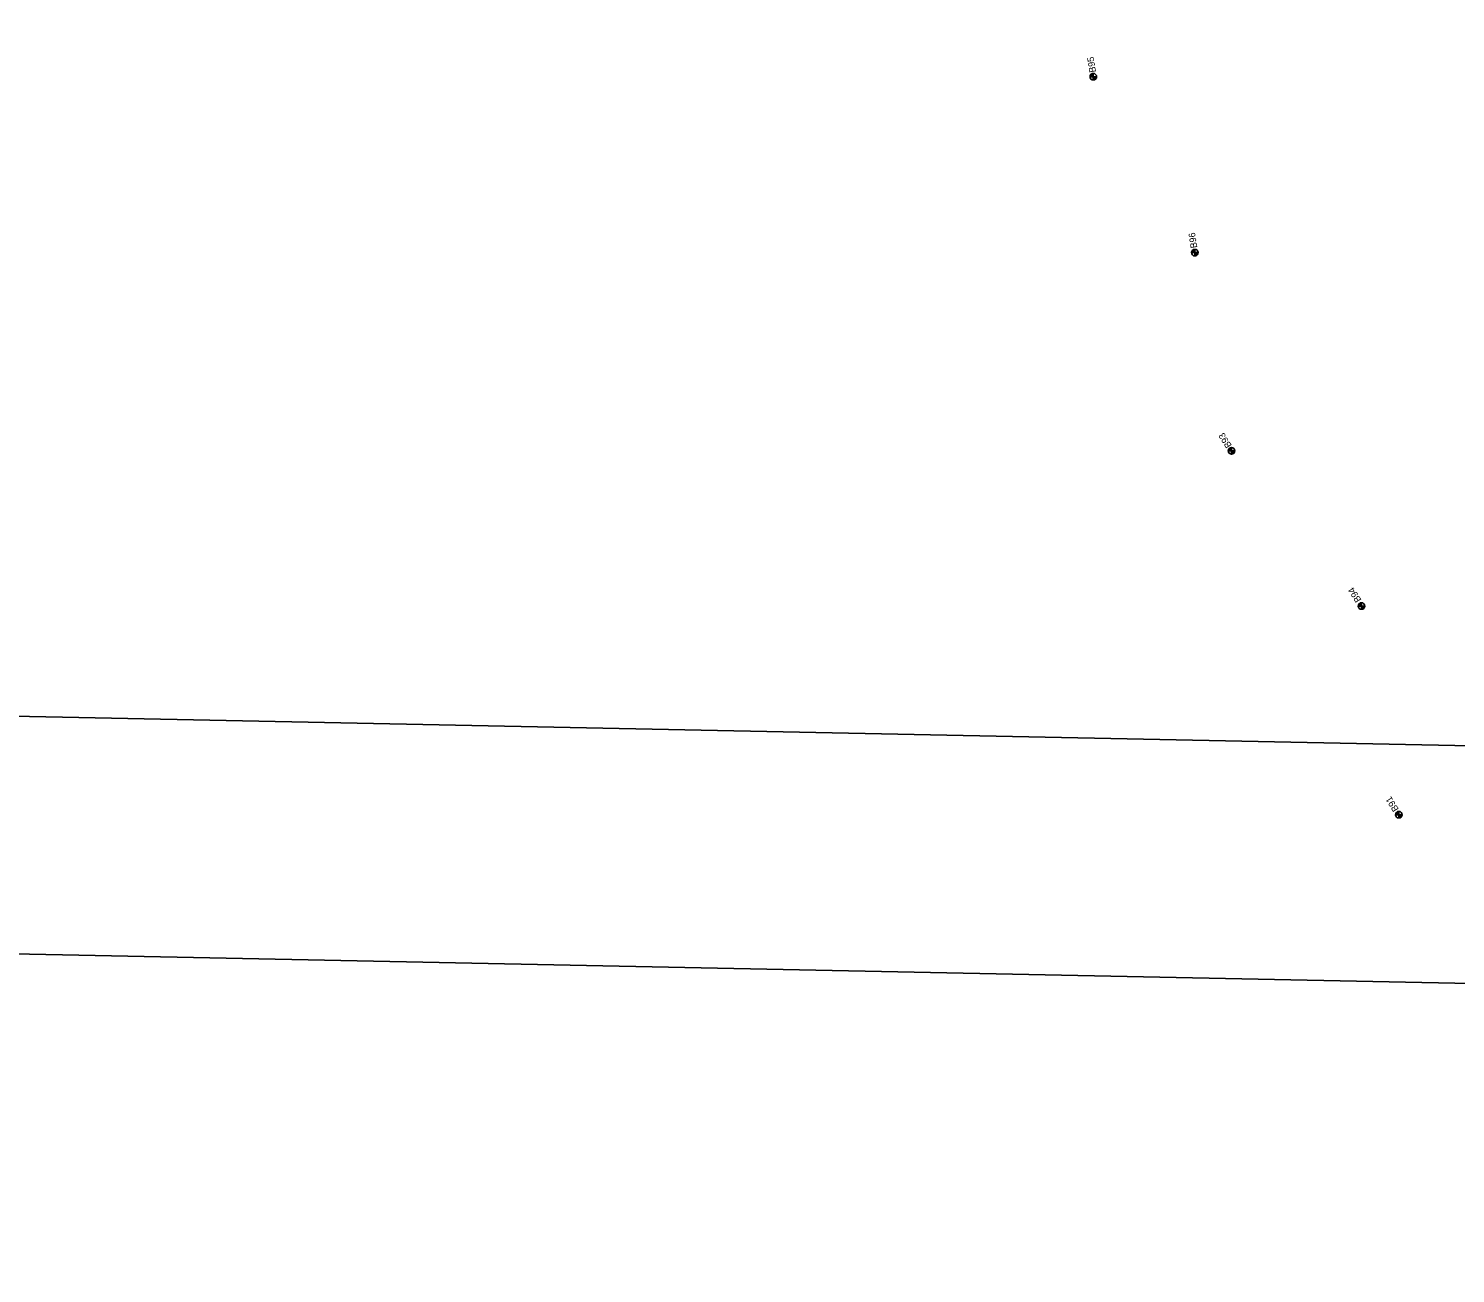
# Model space of a CAD drawing. Extents: x 345549 to 379569, y 127949 to 230467.
# Drawn here: x 354537 to 356698, y 178813 to 180699 of the extents above; entities that cross this region are included whole.
import ezdxf

# ---------------------------------------------------------------- set-up
doc = ezdxf.new("R2010")
doc.units = 0
for name, color, linetype in [('E_SOIL_BORE1 [KAPUR_CADDS_LEVELS]', 7, 'Continuous'), ('E_SOIL_BORE2 [KAPUR_CADDS_LEVELS]', 7, 'Continuous'), ('P_MARK', 7, 'Continuous'), ('P_RDWY_Text', 7, 'Continuous'), ('PLT_Sheet_Border', 7, 'Continuous')]:
    doc.layers.add(name, color=color, linetype=linetype)

msp = doc.modelspace()

# ---------------------------------------------------------------- linework, layer by layer
at = {"layer": 'P_MARK'}
for p, q in [((356149.6, 180631), (356149.6, 180621)), ((356144.6, 180626), (356154.6, 180626)), ((356298.3, 180359.4), (356308.3, 180359.4)), ((356303.3, 180364.4), (356303.3, 180354.4)), ((356354.1, 180059.1), (356364.1, 180059.1)), ((356359.1, 180064.1), (356359.1, 180054.1)), ((356555.7, 179829.1), (356555.7, 179819.1)), ((356550.7, 179824.1), (356560.7, 179824.1)), ((356607.4, 179508), (356617.4, 179508)), ((356612.4, 179513), (356612.4, 179503))]:
    msp.add_line(p, q, dxfattribs=at)
for centre in [(356149.6, 180626), (356303.3, 180359.4), (356359.1, 180059.1), (356555.7, 179824.1), (356612.4, 179508)]:
    msp.add_circle(centre, 5, dxfattribs=at)
for centre, radius, start, end in [((356149.6, 180626), 4.5, 89.9869, 179.9869), ((356149.6, 180626), 4, 89.9869, 179.9869), ((356149.6, 180626), 3.5, 89.9869, 179.9869), ((356149.6, 180626), 3, 89.9869, 179.9869), ((356149.6, 180626), 2.5, 89.9869, 179.9869), ((356149.6, 180626), 2, 89.9869, 179.9869), ((356149.6, 180626), 1.5, 89.9869, 179.9869), ((356149.6, 180626), 1, 89.9869, 179.9869), ((356149.6, 180626), 0.5, 89.9869, 179.9869), ((356149.6, 180626), 4.5, 269.9869, 359.9869), ((356149.6, 180626), 4, 269.9869, 359.9869), ((356149.6, 180626), 3.5, 269.9869, 359.9869), ((356149.6, 180626), 3, 269.9869, 359.9869), ((356149.6, 180626), 2.5, 269.9869, 359.9869), ((356149.6, 180626), 2, 269.9869, 359.9869), ((356149.6, 180626), 1.5, 269.9869, 359.9869), ((356149.6, 180626), 1, 269.9869, 359.9869), ((356149.6, 180626), 0.5, 269.9869, 359.9869), ((356303.3, 180359.4), 4.5, 89.9869, 179.9869), ((356303.3, 180359.4), 4, 89.9869, 179.9869), ((356303.3, 180359.4), 3.5, 89.9869, 179.9869), ((356303.3, 180359.4), 3, 89.9869, 179.9869), ((356303.3, 180359.4), 2.5, 89.9869, 179.9869), ((356303.3, 180359.4), 2, 89.9869, 179.9869), ((356303.3, 180359.4), 1.5, 89.9869, 179.9869), ((356303.3, 180359.4), 1, 89.9869, 179.9869), ((356303.3, 180359.4), 0.5, 89.9869, 179.9869), ((356303.3, 180359.4), 4.5, 269.9869, 359.9869), ((356303.3, 180359.4), 4, 269.9869, 359.9869), ((356303.3, 180359.4), 3.5, 269.9869, 359.9869), ((356303.3, 180359.4), 3, 269.9869, 359.9869), ((356303.3, 180359.4), 2.5, 269.9869, 359.9869), ((356303.3, 180359.4), 2, 269.9869, 359.9869), ((356303.3, 180359.4), 1.5, 269.9869, 359.9869), ((356303.3, 180359.4), 1, 269.9869, 359.9869), ((356303.3, 180359.4), 0.5, 269.9869, 359.9869), ((356359.1, 180059.1), 4.5, 89.9869, 179.9869), ((356359.1, 180059.1), 4, 89.9869, 179.9869), ((356359.1, 180059.1), 3.5, 89.9869, 179.9869), ((356359.1, 180059.1), 3, 89.9869, 179.9869), ((356359.1, 180059.1), 2.5, 89.9869, 179.9869), ((356359.1, 180059.1), 2, 89.9869, 179.9869), ((356359.1, 180059.1), 1.5, 89.9869, 179.9869), ((356359.1, 180059.1), 1, 89.9869, 179.9869), ((356359.1, 180059.1), 0.5, 89.9869, 179.9869), ((356359.1, 180059.1), 4.5, 269.9869, 359.9869), ((356359.1, 180059.1), 4, 269.9869, 359.9869), ((356359.1, 180059.1), 3.5, 269.9869, 359.9869), ((356359.1, 180059.1), 3, 269.9869, 359.9869), ((356359.1, 180059.1), 2.5, 269.9869, 359.9869), ((356359.1, 180059.1), 2, 269.9869, 359.9869), ((356359.1, 180059.1), 1.5, 269.9869, 359.9869), ((356359.1, 180059.1), 1, 269.9869, 359.9869), ((356359.1, 180059.1), 0.5, 269.9869, 359.9869), ((356555.7, 179824.1), 4.5, 89.9869, 179.9869), ((356555.7, 179824.1), 4, 89.9869, 179.9869), ((356555.7, 179824.1), 3.5, 89.9869, 179.9869), ((356555.7, 179824.1), 3, 89.9869, 179.9869), ((356555.7, 179824.1), 2.5, 89.9869, 179.9869), ((356555.7, 179824.1), 2, 89.9869, 179.9869), ((356555.7, 179824.1), 1.5, 89.9869, 179.9869), ((356555.7, 179824.1), 1, 89.9869, 179.9869), ((356555.7, 179824.1), 0.5, 89.9869, 179.9869), ((356555.7, 179824.1), 4.5, 269.9869, 359.9869), ((356555.7, 179824.1), 4, 269.9869, 359.9869), ((356555.7, 179824.1), 3.5, 269.9869, 359.9869), ((356555.7, 179824.1), 3, 269.9869, 359.9869), ((356555.7, 179824.1), 2.5, 269.9869, 359.9869), ((356555.7, 179824.1), 2, 269.9869, 359.9869), ((356555.7, 179824.1), 1.5, 269.9869, 359.9869), ((356555.7, 179824.1), 1, 269.9869, 359.9869), ((356555.7, 179824.1), 0.5, 269.9869, 359.9869), ((356612.4, 179508), 4.5, 89.9869, 179.9869), ((356612.4, 179508), 4, 89.9869, 179.9869), ((356612.4, 179508), 3.5, 89.9869, 179.9869), ((356612.4, 179508), 3, 89.9869, 179.9869), ((356612.4, 179508), 2.5, 89.9869, 179.9869), ((356612.4, 179508), 2, 89.9869, 179.9869), ((356612.4, 179508), 1.5, 89.9869, 179.9869), ((356612.4, 179508), 1, 89.9869, 179.9869), ((356612.4, 179508), 0.5, 89.9869, 179.9869), ((356612.4, 179508), 4.5, 269.9869, 359.9869), ((356612.4, 179508), 4, 269.9869, 359.9869), ((356612.4, 179508), 3.5, 269.9869, 359.9869), ((356612.4, 179508), 3, 269.9869, 359.9869), ((356612.4, 179508), 2.5, 269.9869, 359.9869), ((356612.4, 179508), 2, 269.9869, 359.9869), ((356612.4, 179508), 1.5, 269.9869, 359.9869), ((356612.4, 179508), 1, 269.9869, 359.9869), ((356612.4, 179508), 0.5, 269.9869, 359.9869)]:
    msp.add_arc(centre, radius, start, end, dxfattribs=at)
at = {"layer": 'P_RDWY_Text'}
msp.add_lwpolyline([(345549, 179477.5), (346575.9, 230467.1), (379569.2, 229802.6), (378542.3, 178813)], close=True, dxfattribs=at)
at = {"layer": 'PLT_Sheet_Border'}
for points in [[(378542.3, 178813), (379569.2, 229802.6), (346575.9, 230467.1), (345549, 179477.5)], [(377799.7, 179188), (378799.5, 228827.9), (347305.8, 229462.2), (346306.1, 179822.3)]]:
    msp.add_lwpolyline(points, close=True, dxfattribs=at)

# ---------------------------------------------------------------- texts
at = {"layer": 'E_SOIL_BORE1 [KAPUR_CADDS_LEVELS]'}
msp.add_text('B95', height=10, rotation=98.957, dxfattribs=at).set_placement((356153.7, 180633.1))
at = {"layer": 'E_SOIL_BORE2 [KAPUR_CADDS_LEVELS]'}
for s, rotation, p in [('B96', 98.957, (356307.2, 180367)), ('B93', 121.7799, (356359.7, 180067.3)), ('B94', 121.7799, (356556, 179833.4)), ('B91', 121.7799, (356612.7, 179516.4))]:
    msp.add_text(s, height=10, rotation=rotation, dxfattribs=at).set_placement(p)

doc.saveas('drawing.dxf')
